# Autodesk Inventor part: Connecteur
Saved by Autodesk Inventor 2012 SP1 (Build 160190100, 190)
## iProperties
Created: 2014-12
Part Number: Connecteur
Material: Default
Document SubType Name: Modeling
Designer: Bruno
Density: 1 g/cm^3
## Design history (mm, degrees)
node "Connecteur1"
node "Connecteur"
node "Base1"
